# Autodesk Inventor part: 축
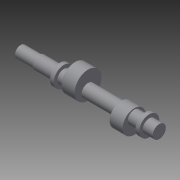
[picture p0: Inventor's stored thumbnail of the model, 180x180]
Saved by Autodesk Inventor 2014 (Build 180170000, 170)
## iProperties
Created: 2014-12
Part Number: 축
Material: 일반
Document SubType Name: Modeling
Designer: Owner
Density: 1 g/cm^3
Appearance: 기본값
Author: Owner
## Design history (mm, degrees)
sketch "스케치1"
  geometry: L1 (-90, 0)-(90, 0); L2 (-90, 0)-(-90, 7.5); L3 (-90, 7.5)-(-66, 7.5); L4 (-66, 7.5)-(-66, 8.5); L5 (-66, 8.5)-(-39, 8.5); L6 (-39, 8.5)-(-39, 13); L7 (-39, 13)-(-34, 13); L8 (-34, 13)-(-34, 8.5); L9 (-34, 8.5)-(72, 8.5); L10 (72, 8.5)-(72, 13); L11 (72, 13)-(77, 13); L12 (77, 13)-(77, 8.5); L13 (77, 8.5)-(90, 8.5); L14 (90, 8.5)-(90, 0); 2 further points
  constraints: 28 end point, 11 parallel, 2 horizontal alignment, 2 perpendicular, 1 coincident, 1 horizontal, 1 midpoint
  dimensions: "d12" = 180 distance of L1.start L1.end; "d13" = 15 diameter of L3 L1; "d14" = 17 diameter of L5 L1; "d15" = 24 distance of L2.end L3.end; "d16" = 26 diameter of L7 L1; "d17" = 5 distance of L6.end L7.end; "d18" = 27 distance of L4.end L5.end; "d19" = 13 distance of L12.end L13.end; "d20" = 5 distance of L10.end L11.end; "d21" = 26 diameter of L11 L1
revolve "회전1" sketch "스케치1" stored, may be unused: angle "d22" = 90 deg
node "작업 평면1"
sketch "스케치2"
  geometry: C1 r 17.5 at (-6, 0); 1 further point
  constraints: 1 centre point, 1 horizontal alignment
  dimensions: "d24" = 35 diameter of C1; "d25" = 6 distance of point (0, 0) C1.centre
extrude "돌출1" join sketch "스케치2" distance "d26" = 17; taper "d27" = 0 deg
node "작업 평면2"
sketch "스케치3"
  geometry: C1 r 15 at (-5, 0); 1 further point
  constraints: 1 centre point, 1 horizontal alignment
  dimensions: "d29" = 30 diameter of C1; "d30" = 5 distance of point (0, 0) C1.centre
extrude "돌출2" join sketch "스케치3" distance "d31" = 17; taper "d32" = 0 deg
node "솔리드1"
other parameters: "d23" = 14.5, "d28" = 14.5
